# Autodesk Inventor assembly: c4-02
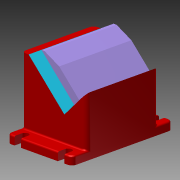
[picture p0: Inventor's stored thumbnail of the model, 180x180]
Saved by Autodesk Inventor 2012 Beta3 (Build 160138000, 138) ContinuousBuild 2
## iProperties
Created: 2010-11
Part Number: c4-02
Document SubType Name: Assembly
Designer: Beta-8540w
Author: Beta-8540w
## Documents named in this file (3)
- C:\Inventor 2012 Essentials\Assemblies\Chapter 4\c4-02.iam
- C:\Inventor 2012 Essentials\Parts\Chapter 4\c4-01.ipt
- C:\Inventor 2012 Essentials\Parts\Chapter 4\c4-02.ipt
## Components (2 placed, 2 different names)
1. c4-01:1 — Mate:1, Mate:2
2. c4-02:1 — Mate:1, Mate:2
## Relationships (2: Mate 2)
- Mate:1: c4-01:1 ↔ c4-02:1
- Mate:2: c4-01:1 ↔ c4-02:1
